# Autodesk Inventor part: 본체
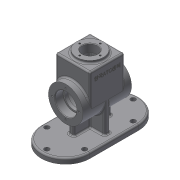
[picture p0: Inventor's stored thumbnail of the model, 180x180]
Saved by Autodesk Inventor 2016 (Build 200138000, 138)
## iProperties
Created: 2019-01
Part Number: 본체
Material: 알루미늄 6061
Document SubType Name: Modeling
Designer: mduedu
Density: 2.71 g/cm^3
Mass: 1057.72 g
Surface Area: 916.19 cm^2
Volume: 390.301 cm^3
Appearance: 기본값
Author: mduedu
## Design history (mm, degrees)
sketch "스케치1"
  geometry: C1 r 32 at (0, 0); 1 further point
  constraints: 1 centre point, 1 coincident
  dimensions: "d0" = 64 diameter of C1
extrude "돌출1" new body sketch "스케치1" stored distance "d1" = 90; taper "d2" = 0 deg
sketch "스케치2"
  geometry: L1 (0, 32)-(60, 32); L2 (60, 32)-(60, -32); L3 (60, -32)-(0, -32); L4 (0, -32)-(0, 32); C1 r 32 at (0, 0) reference; 2 further points
  constraints: 8 end point, 2 parallel, 1 coincident, 1 horizontal, 1 midpoint, 1 perpendicular, 1 tangent
  dimensions: "d5" = 60 distance between parallel lines of L4 L2
extrude "돌출2" join sketch "스케치2" stored distance "d7" = 64; taper "d8" = 0 deg
sketch "스케치3"
  geometry: C1 r 25 at (32, 32); 1 further point
  constraints: 1 centre point, 1 coincident
  dimensions: "d9" = 50 diameter of C1
extrude "돌출3" join sketch "스케치3" distance "d10" = 5; taper "d11" = 0 deg
sketch "스케치4"
  geometry: L1 (50, 25)-(0, 25); L2 (0, 25)-(0, -25); L3 (0, -25)-(50, -25); L4 (50, -25)-(50, 25); L5 (65, -25)-(65, 25) reference; A1 r 25 centre (0, 0) between (0, 25) and (0, -25); A2 r 25 centre (0, 0) between (0, -25) and (0, 25); 2 further points
  constraints: 8 end point, 4 point on circle, 2 centre point, 2 coincident, 2 parallel, 1 horizontal, 1 midpoint, 1 perpendicular, 1 tangent
  dimensions: "d12" = 50 diameter of A1; "d13" = 15 distance between parallel lines of L4 L5
extrude "돌출4" cut sketch "스케치4" stored distance "d14" = 48; taper "d15" = 0 deg
sketch "스케치5"
  geometry: C1 r 20 at (0, 0); 1 further point
  constraints: 1 centre point, 1 coincident
  dimensions: "d16" = 40 diameter of C1
extrude "돌출5" cut sketch "스케치5" distance "d17" = 15; taper "d18" = 0 deg
sketch "스케치6"
  geometry: C1 r 17 at (0, 0); 1 further point
  constraints: 1 centre point, 1 coincident
  dimensions: "d19" = 34 diameter of C1
extrude "돌출6" cut sketch "스케치6" stored distance "d20" = 15; taper "d21" = 0 deg
fillet "모깎기1" dims "d22" = 0.3
fillet "모깎기2" dims "d23" = 3
fillet "모깎기3" dims "d24" = 3
fillet "모깎기4" dims "d25" = 3
fillet "모깎기5" dims "d26" = 3
fillet "모깎기6" dims "d27" = 3
sketch "스케치7"
  geometry: C1 r 14 at (0, 0); 1 further point
  constraints: 1 centre point, 1 coincident
  dimensions: "d28" = 28 diameter of C1
extrude "돌출7" cut sketch "스케치7" stored distance "d29" = 15; taper "d30" = 0 deg
chamfer "모따기1" distance "d31" = 1; stored, may be unused: second distance "d32" = 2, angle "d33" = 45 deg
chamfer "모따기2" distance "d34" = 1; stored, may be unused: second distance "d35" = 2, angle "d36" = 45 deg
node "작업 평면1"
sketch "스케치8"
  geometry: L1 (45, 45)-(-45, 45); L2 (-45, 45)-(-45, -45); L3 (-45, -45)-(45, -45); L4 (45, -45)-(45, 45); L5 (45, 45)-(-45, -45); L6 (-45, 45)-(45, -45); A1 r 45 centre (45, 0) between (45, -45) and (45, 45); A2 r 45 centre (-45, 0) between (-45, 45) and (-45, -45); A3 r 45 centre (45, 0) between (0, 0) and (45, -45); A4 r 45 centre (45, 0) between (0, 0) and (0, 0); A5 r 45 centre (45, 0) between (45, 45) and (0, 0); A6 r 45 centre (-45, 0) between (0, 0) and (-45, 45); A7 r 45 centre (-45, 0) between (-45, -45) and (0, 0); 1 further point
  constraints: 14 point on circle, 12 end point, 7 centre point, 7 midpoint, 2 parallel, 1 horizontal, 1 perpendicular
  dimensions: "d99" = 90 distance between parallel lines of L1 L3; "d101" = 90 distance between parallel lines of L2 L4
extrude "돌출8" join sketch "스케치8" distance "d41" = 10; taper "d42" = 0 deg
sketch "스케치9"
  geometry: L1 (-35, 5)-(35, 5); L2 (35, 5)-(35, -5); L3 (35, -5)-(-35, -5); L4 (-35, -5)-(-35, 5); 3 further points
  constraints: 8 end point, 2 midpoint, 2 parallel, 1 horizontal, 1 horizontal alignment, 1 perpendicular, 1 vertical alignment
  dimensions: "d52" = 10 distance of L1.end L2.end; "d54" = 70 distance of L1.start L1.end
extrude "돌출9" join sketch "스케치9" stored distance "d50" = 10; taper "d51" = 0 deg
sketch "스케치10"
  geometry: L1 (0, -25)-(47, -25) reference; L2 (50, -22)-(50, -14) reference; L3 (50, -14)-(64, -14) reference; L4 (64, -14)-(65, -15) reference; L5 (65, -15)-(65, -25) reference; L6 (65, -25)-(63, -25) reference; L7 (60, -28)-(60, -29) reference; L8 (57, -32)-(0, -32) reference; L9 (-31.607, -5)-(-55, -5) reference; L10 (-55, -5)-(-55, -45) reference; L11 (-65, -45)-(-65, 45) reference; L12 (-55, 45)-(-55, 5) reference; L13 (-55, 5)-(-31.607, 5) reference; L14 (0, 32)-(57, 32) reference; L15 (60, 29)-(60, 28) reference; L16 (63, 25)-(65, 25) reference; L17 (65, 25)-(65, 15) reference; L18 (65, 15)-(64, 14) reference; L19 (64, 14)-(50, 14) reference; L20 (50, 14)-(50, 22) reference; L21 (47, 25)-(0, 25) reference; L22 (-55, -45)-(-65, -45) reference; L23 (-65, 45)-(-55, 45) reference; L24 (0, 32)-(-55, 32); A1 r 25 centre (0, 0) between (0, 25) and (0, -25) reference; A2 r 3 centre (47, -22) between (47, -25) and (50, -22) reference; A3 r 3 centre (63, -28) between (63, -25) and (60, -28) reference; A4 r 3 centre (57, -29) between (57, -32) and (60, -29) reference; A5 r 32 centre (0, 0) between (-31.607, -5) and (0, -32) reference; A6 r 32 centre (0, 0) between (0, 32) and (-31.607, 5) reference; A7 r 3 centre (57, 29) between (60, 29) and (57, 32) reference; A8 r 3 centre (63, 28) between (60, 28) and (63, 25) reference; A9 r 3 centre (47, 22) between (50, 22) and (47, 25) reference
  constraints: 2 end point, 1 perpendicular, 1 point on line, 1 tangent
feature "리브1" sketch "스케치10" dims "d57" = 1, "d58" = 10, "d59" = 0, "d60" = 0, "d61" = 1, "d62" = 1
fillet "모깎기7" dims "d63" = 3
fillet "모깎기11" dims "d102" = 3
fillet "모깎기8" dims "d64" = 3
sketch "스케치11"
  geometry: L1 (8, -29)-(8, -8) reference; L2 (-8, -8)-(-8, -29) reference; L3 (-32, -8)-(-8, -8) reference; L4 (-38, 2)-(-38, -2) reference; L5 (-8, 8)-(-32, 8) reference; L6 (-8, 29)-(-8, 8) reference; L7 (8, 8)-(8, 29) reference; L8 (32, 8)-(8, 8) reference; L9 (38, -2)-(38, 2) reference; L10 (8, -8)-(32, -8) reference; L11 (-2, -35)-(2, -35) reference; L12 (2, 35)-(-2, 35) reference; L13 (-45, -45)-(45, -45) reference; L14 (45, 45)-(-45, 45) reference; L15 (-45, -35)-(45, -35); L16 (45, 35)-(-45, 35); A1 r 6 centre (-32, -2) between (-38, -2) and (-32, -8) reference; A2 r 6 centre (-32, 2) between (-32, 8) and (-38, 2) reference; A3 r 6 centre (32, 2) between (38, 2) and (32, 8) reference; A4 r 6 centre (32, -2) between (32, -8) and (38, -2) reference; A5 r 6 centre (2, -29) between (2, -35) and (8, -29) reference; A6 r 6 centre (-2, -29) between (-8, -29) and (-2, -35) reference; A7 r 6 centre (-2, 29) between (-2, 35) and (-8, 29) reference; A8 r 6 centre (2, 29) between (8, 29) and (2, 35) reference; A9 r 45 centre (-45, 0) between (-45, 45) and (-45, -45) reference; A10 r 45 centre (45, 0) between (45, -45) and (45, 45) reference; A11 r 35 centre (-45, 0) between (-45, 35) and (-45, -35); A12 r 35 centre (45, 0) between (45, -35) and (45, 35); 7 further points
  constraints: 6 point on circle, 4 coincident, 4 end point, 2 centre point, 3 other
  dimensions: "d103" = 10 distance between parallel lines of L16 L14
hole "구멍1" sketch "스케치11" at (-45, 35), (-80, 0), (-45, -35), (45, -35), (80, 0), (45, 35) diameter "d66" = 9; stored, may be unused: countersink angle "d70" = 90 deg, drill point angle "d72" = 118 deg; dims "d67" = 6, "d68" = 4, "d69" = 2, "d71" = 8
fillet "모깎기10" dims "d73" = 3
sketch "스케치12"
  geometry: L1 (-3, 57)-(-3, 19.596) reference; 2 further points
  constraints: 1 other
  dimensions: "d74" = 32 distance from line of point (29, 45) L1; "d75" = 45 distance of point (29, 45) point (29, 0)
feature "엠보싱1" sketch "스케치12" dims "d12" = 50, "d13" = 15, "d76" = 0.5, "d77" = 0
sketch "스케치13"
  geometry: 4 further points
  constraints: 4 other
hole "구멍2" sketch "스케치13" at (-25, 0), (0, -25), (25, 0), (0, 25) diameter "d78" = 3.242; stored, may be unused: countersink angle "d82" = 90 deg, drill point angle "d84" = 120 deg; dims "d79" = 7, "d80" = 4, "d81" = 2, "d83" = 9
sketch "스케치14"
  geometry: 4 further points
  constraints: 4 other
hole "구멍3" sketch "스케치14" at (-25, 0), (0, -25), (25, 0), (0, 25) diameter "d85" = 3.242; stored, may be unused: countersink angle "d89" = 90 deg, drill point angle "d91" = 120 deg; dims "d86" = 7, "d87" = 4, "d88" = 2, "d90" = 9
sketch "스케치15"
  geometry: 4 further points
  constraints: 4 other
hole "구멍4" sketch "스케치15" at (0, -19), (19, 0), (0, 19), (-19, 0) diameter "d92" = 3.242; stored, may be unused: countersink angle "d96" = 90 deg, drill point angle "d98" = 120 deg; dims "d93" = 8, "d94" = 4, "d95" = 2, "d97" = 10
node "솔리드1"
mirror "대칭1"
mirror "대칭2"
node "투영된 루프1"
node "투영된 루프2"
node "절단 모서리 투영1"
node "절단 모서리 투영2"
other parameters: "d37" = -65
